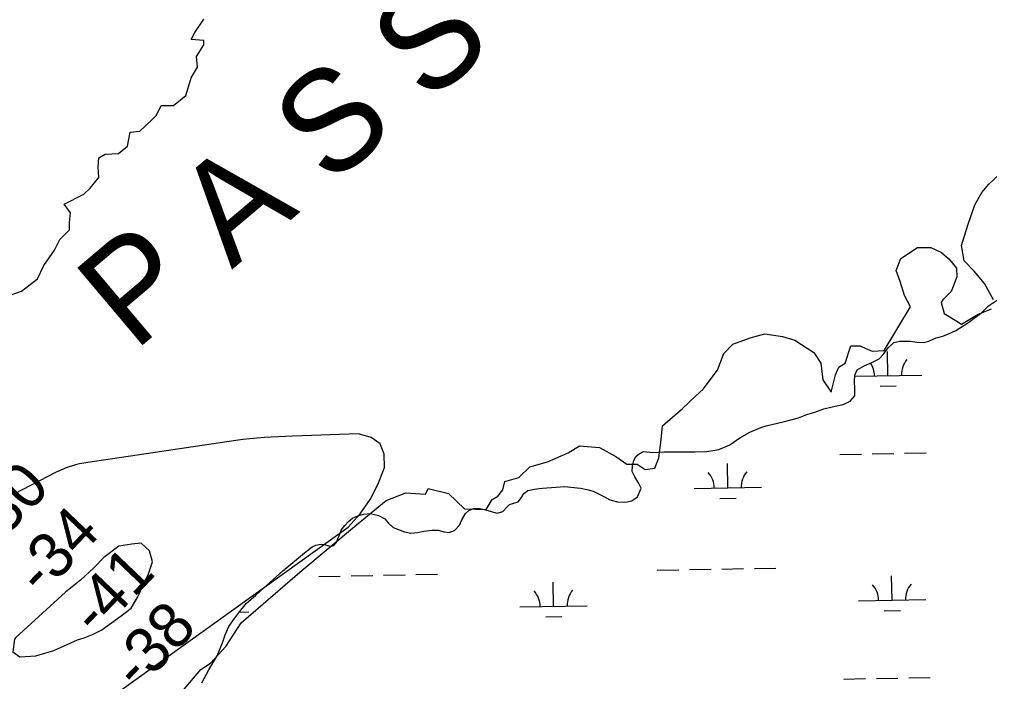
# Model space of a CAD drawing. Extents: x 3957609 to 3995875, y 234277 to 260273.
# Drawn here: x 3963753 to 3965192, y 243483 to 244464 of the extents above; entities that cross this region are included whole.
import ezdxf

# ---------------------------------------------------------------- set-up
doc = ezdxf.new("R2010")
doc.units = 0
for name, color, linetype in [('V-RIVR-EDGE', 7, 'Continuous'), ('V-RIVR-IDEN', 7, 'Continuous'), ('V-RIVR-RANG', 7, 'Continuous'), ('V-TOPO-MINR', 7, 'Continuous'), ('V-WETL-SWMP', 7, 'Continuous')]:
    doc.layers.add(name, color=color, linetype=linetype)

msp = doc.modelspace()

# ---------------------------------------------------------------- linework, layer by layer
at = {"layer": 'V-RIVR-EDGE'}
for points in [[(3963734.378, 244053.177), (3963756.764, 244061.078), (3963780.466, 244079.513), (3963789.684, 244099.265), (3963805.486, 244121.651), (3963813.386, 244137.453), (3963827.871, 244151.937), (3963827.871, 244162.472), (3963829.188, 244176.957), (3963819.97, 244190.125), (3963848.94, 244204.61), (3963858.158, 244213.827), (3963871.326, 244229.629), (3963870.009, 244245.431), (3963871.326, 244258.599), (3963880.544, 244263.866), (3963900.296, 244265.183), (3963913.464, 244275.717), (3963917.414, 244296.786), (3963931.899, 244298.103), (3963950.334, 244315.221), (3963956.918, 244321.805), (3963963.502, 244336.29), (3963981.938, 244336.29), (3964000.373, 244350.775), (3964004.323, 244363.943), (3964008.274, 244377.111), (3964017.491, 244392.913), (3964016.175, 244408.715), (3964026.709, 244425.833), (3964026.709, 244432.417), (3964008.274, 244433.734), (3964013.541, 244444.268), (3964026.709, 244464.02)], [(3965197.452, 244048.071), (3965184.196, 244072.69), (3965169.046, 244090.68), (3965153.896, 244105.83), (3965150.109, 244128.555), (3965159.577, 244158.855), (3965169.993, 244189.154), (3965180.408, 244207.145), (3965190.824, 244219.454), (3965205.027, 244232.71)], [(3964445.511, 243737.513), (3964454.163, 243752.65), (3964462.685, 243757.384), (3964470.26, 243766.853), (3964473.1, 243779.162), (3964493.931, 243784.843), (3964510.028, 243800.94), (3964536.54, 243808.515), (3964566.84, 243821.771), (3964583.884, 243832.186), (3964613.236, 243829.346), (3964637.855, 243816.089), (3964653.952, 243804.727), (3964669.101, 243804.727), (3964681.411, 243797.152), (3964695.614, 243799.046), (3964701.295, 243814.196), (3964705.082, 243840.708), (3964706.976, 243861.539), (3964736.329, 243887.104), (3964755.266, 243905.095), (3964767.575, 243916.457), (3964778.938, 243931.607), (3964788.406, 243943.916), (3964797.875, 243968.535), (3964811.131, 243982.738), (3964836.696, 243992.206), (3964858.474, 243997.888), (3964884.987, 243994.1), (3964902.977, 243988.419), (3964931.383, 243970.428), (3964941.798, 243954.332), (3964944.639, 243929.713), (3964956.948, 243911.723), (3964963.576, 243937.288), (3964968.311, 243948.651), (3964977.779, 243954.332), (3964986.301, 243979.897), (3964999.557, 243979.897), (3965017.548, 243972.322), (3965035.538, 243973.269), (3965074.36, 244037.656), (3965065.838, 244054.699), (3965059.21, 244075.531), (3965053.529, 244091.627), (3965060.157, 244109.618), (3965084.775, 244125.714), (3965104.659, 244125.714), (3965120.756, 244118.139), (3965132.118, 244108.671), (3965142.534, 244095.415), (3965143.481, 244082.159), (3965137.8, 244067.956), (3965134.959, 244060.381), (3965122.65, 244048.071), (3965119.809, 244044.284), (3965124.543, 244028.187), (3965143.481, 244016.825), (3965150.109, 244012.091), (3965174.727, 244027.24), (3965194.611, 244034.815)], [(3963981.677, 243452.493), (3964022.393, 243500.783), (3964036.596, 243510.252), (3964059.32, 243534.871), (3964082.045, 243569.905), (3964169.157, 243644.707), (3964253.428, 243714.775), (3964296.983, 243750.756), (3964326.336, 243762.118), (3964340.539, 243761.171), (3964355.689, 243760.224), (3964359.476, 243768.746), (3964389.776, 243761.171), (3964413.448, 243738.447), (3964444.694, 243737.5), (3964445.641, 243737.5)]]:
    msp.add_lwpolyline(points, dxfattribs=at)
at = {"layer": 'V-TOPO-MINR'}
msp.add_lwpolyline([(3963060.899, 242865.926), (3964240.98, 243711.482), (3964258.488, 243731.174), (3964273.674, 243752.275), (3964285.377, 243775.489), (3964294.757, 243800.113), (3964294.003, 243819.42), (3964288.174, 243834.787), (3964274.733, 243844.245), (3964256.217, 243849.764), (3964158.267, 243846.415), (3964147.755, 243846.002), (3964137.248, 243845.518), (3964126.745, 243844.928), (3964116.247, 243844.267), (3964105.764, 243843.428), (3964095.299, 243842.426), (3964084.861, 243841.176), (3964074.44, 243839.762), (3963854.783, 243807.314), (3963848.734, 243806.289), (3963842.722, 243805.094), (3963836.766, 243803.646), (3963830.847, 243802.028), (3963825.021, 243800.123), (3963819.279, 243798.005), (3963813.665, 243795.57), (3963808.136, 243792.923), (3963745.183, 243760.586)], dxfattribs=at)
msp.add_lwpolyline([(3963804.335, 243528.957), (3963839.32, 243544.717), (3963849.348, 243547.42), (3963861.85, 243552.688), (3963875.587, 243559.24), (3963904.184, 243579.925), (3963919.089, 243591.539), (3963928.866, 243608.1), (3963937.337, 243627.159), (3963944.618, 243642.416), (3963950.593, 243660.169), (3963946.518, 243676.479), (3963933.719, 243687.589), (3963919.89, 243686.077), (3963901.046, 243683.214), (3963878.677, 243666.423), (3963863.841, 243651.029), (3963844.013, 243633.024), (3963821.667, 243614.974), (3963748.215, 243547.801), (3963746.019, 243545.395), (3963743.913, 243526.598), (3963754.125, 243519.221), (3963778.028, 243520.916)], close=True, dxfattribs=at)
at = {"layer": 'V-WETL-SWMP'}
for p, q in [((3965041.194, 243935.881), (3965040.539, 243971.875)), ((3964991.79, 243934.983), (3965091.185, 243936.79)), ((3965029.476, 243920.235), (3965053.472, 243920.671)), ((3964969.896, 243819.134), (3965001.891, 243819.716)), ((3965017.888, 243820.007), (3965049.883, 243820.588)), ((3965065.881, 243820.879), (3965097.875, 243821.461)), ((3964803.704, 243769.674), (3964803.05, 243805.668)), ((3964753.712, 243768.765), (3964853.696, 243770.583)), ((3964791.987, 243754.028), (3964815.983, 243754.464)), ((3964795.045, 243649.426), (3964827.04, 243650.008)), ((3964843.037, 243650.299), (3964875.032, 243650.88)), ((3964197.236, 243638.556), (3964229.23, 243639.138)), ((3964245.228, 243639.429), (3964277.222, 243640.01)), ((3964293.22, 243640.301), (3964325.214, 243640.883)), ((3964341.212, 243641.174), (3964373.207, 243641.756)), ((3964699.061, 243647.681), (3964731.055, 243648.263)), ((3964747.053, 243648.553), (3964779.047, 243649.135)), ((3965047.242, 243603.261), (3965046.587, 243639.255)), ((3964545.417, 243594.137), (3964544.762, 243630.131)), ((3964495.425, 243593.228), (3964595.408, 243595.046)), ((3964997.25, 243602.352), (3965097.234, 243604.17)), ((3964079.161, 243585.659), (3964093.583, 243585.921)), ((3964533.699, 243578.49), (3964557.695, 243578.926)), ((3965035.524, 243587.615), (3965059.52, 243588.051)), ((3964975.944, 243486.514), (3965007.939, 243487.096)), ((3965023.937, 243487.387), (3965055.931, 243487.968)), ((3965071.929, 243488.259), (3965103.923, 243488.841))]:
    msp.add_line(p, q, dxfattribs=at)
for points in [[(3964678.607, 243823.425), (3964692.603, 243822.332), (3964709.018, 243823.286), (3964721.53, 243822.987), (3964739.16, 243823.203), (3964754.686, 243822.94), (3964772.46, 243823.61), (3964790.509, 243826.543), (3964806.854, 243833.223), (3964821.492, 243843.951), (3964836.31, 243852.271), (3964852.503, 243859.099), (3964860.763, 243861.461), (3964887.959, 243868.123), (3964908.391, 243873.346), (3964920.84, 243878.17), (3964932.698, 243882.082), (3964946.055, 243886.616), (3964958.374, 243889.781), (3964974.606, 243893.445), (3964985.096, 243898.245), (3964991.932, 243906.166), (3964991.959, 243916.263), (3964991.523, 243927.259), (3964991.857, 243936.908), (3964995.534, 243944.338), (3965005.858, 243950.492), (3965017.249, 243955.605), (3965027.883, 243961.009), (3965033.985, 243967.263), (3965042.147, 243977.61), (3965049.894, 243984.939), (3965058.91, 243987.159), (3965074.582, 243987.2), (3965084.099, 243985.357), (3965093.748, 243985.023), (3965101.712, 243986.929), (3965112.653, 243991.885), (3965122.267, 243994.414), (3965130.816, 243997.834), (3965141.758, 244002.639), (3965151.176, 244008.933), (3965159.257, 244013.553), (3965180.314, 244029.333), (3965190.286, 244039.552), (3965206.734, 244050.152)], [(3964023.72, 243481.025), (3964034.507, 243499.942), (3964046.769, 243520.688), (3964054.41, 243540.246), (3964058.299, 243552.175), (3964064.006, 243564.116), (3964072.192, 243576.238), (3964079.566, 243586.206), (3964090.229, 243598.675), (3964103.214, 243610.168), (3964110.61, 243616.664), (3964143.972, 243646.642), (3964176.033, 243673.47), (3964180.474, 243676.806), (3964187.383, 243682.141), (3964192.986, 243684.824), (3964197.772, 243686.012), (3964203.226, 243686.214), (3964207.034, 243685.412), (3964212.17, 243683.793), (3964215.646, 243683.155), (3964219.77, 243684.504), (3964223.052, 243688.163), (3964225.492, 243694.131), (3964227.933, 243700.098), (3964230.698, 243706.895), (3964235.776, 243714.037), (3964241.359, 243719.86), (3964247.442, 243724.86), (3964255.189, 243728.382), (3964263.771, 243730.588), (3964274.178, 243731.814), (3964285.607, 243728.583), (3964295.062, 243723.686), (3964300.89, 243717.442), (3964307.379, 243711.038), (3964324.121, 243704.37), (3964333.886, 243702.616), (3964343.798, 243703.673), (3964353.21, 243705.388), (3964365.432, 243707.122), (3964374.196, 243706.849), (3964383.304, 243704.595), (3964390.418, 243703.815), (3964398.5, 243706.514), (3964405.887, 243714.498), (3964409.474, 243722.126), (3964414.702, 243731.584), (3964419.631, 243736.246), (3964426.721, 243738.937), (3964435.316, 243739.325), (3964442.766, 243737.721), (3964453.035, 243734.813), (3964461.979, 243732.227), (3964470.393, 243734.762), (3964476.465, 243741.58), (3964480.08, 243744.91), (3964493.115, 243748.799), (3964497.701, 243755.277), (3964501.133, 243761.251), (3964507.387, 243765.59), (3964516.961, 243767.803), (3964524.062, 243769.007), (3964529.184, 243769.371), (3964548.848, 243770.823), (3964562.067, 243771.737), (3964571.165, 243770.971), (3964585.227, 243769.41), (3964594.831, 243767.159), (3964603.94, 243764.574), (3964614.056, 243759.847), (3964620.858, 243756.254), (3964628.821, 243752.009), (3964640.084, 243748.777), (3964652.153, 243748.691), (3964661.234, 243750.569), (3964669.956, 243756.578), (3964675.329, 243769.013), (3964671.646, 243776.097), (3964665.629, 243785.977), (3964662.105, 243793.889), (3964662.379, 243802.487), (3964664.477, 243810.271), (3964667.906, 243816.741), (3964672.346, 243820.242), (3964678.607, 243823.425)]]:
    msp.add_lwpolyline(points, dxfattribs=at)
for centre, start, end in [((3964985.951, 243935.352), 0.269879, 33.415545), ((3965096.419, 243937.36), 140.269876, 181.813534), ((3964858.929, 243771.153), 140.269876, 181.813534), ((3964748.462, 243769.145), 0.269879, 41.813537), ((3964991.999, 243602.732), 0.269879, 41.813537), ((3965102.467, 243604.74), 140.269876, 181.813534), ((3964490.174, 243593.607), 0.269879, 41.813537), ((3964600.642, 243595.616), 140.269876, 181.813534)]:
    msp.add_arc(centre, 35.246, start, end, dxfattribs=at)

# ---------------------------------------------------------------- texts
at = {"layer": 'V-RIVR-IDEN'}
msp.add_text('P A S S', height=149.9997, rotation=40.1698, dxfattribs=at).set_placement((3963923.472, 243970.457))
at = {"layer": 'V-RIVR-RANG'}
for s, p in [('-30', (3963711.798, 243674.466)), ('-34', (3963786.566, 243607.859)), ('-41', (3963867.613, 243548.176)), ('-38', (3963929.41, 243467.627))]:
    msp.add_text(s, height=67, rotation=46.349806, dxfattribs=at).set_placement(p)

doc.saveas('drawing.dxf')
